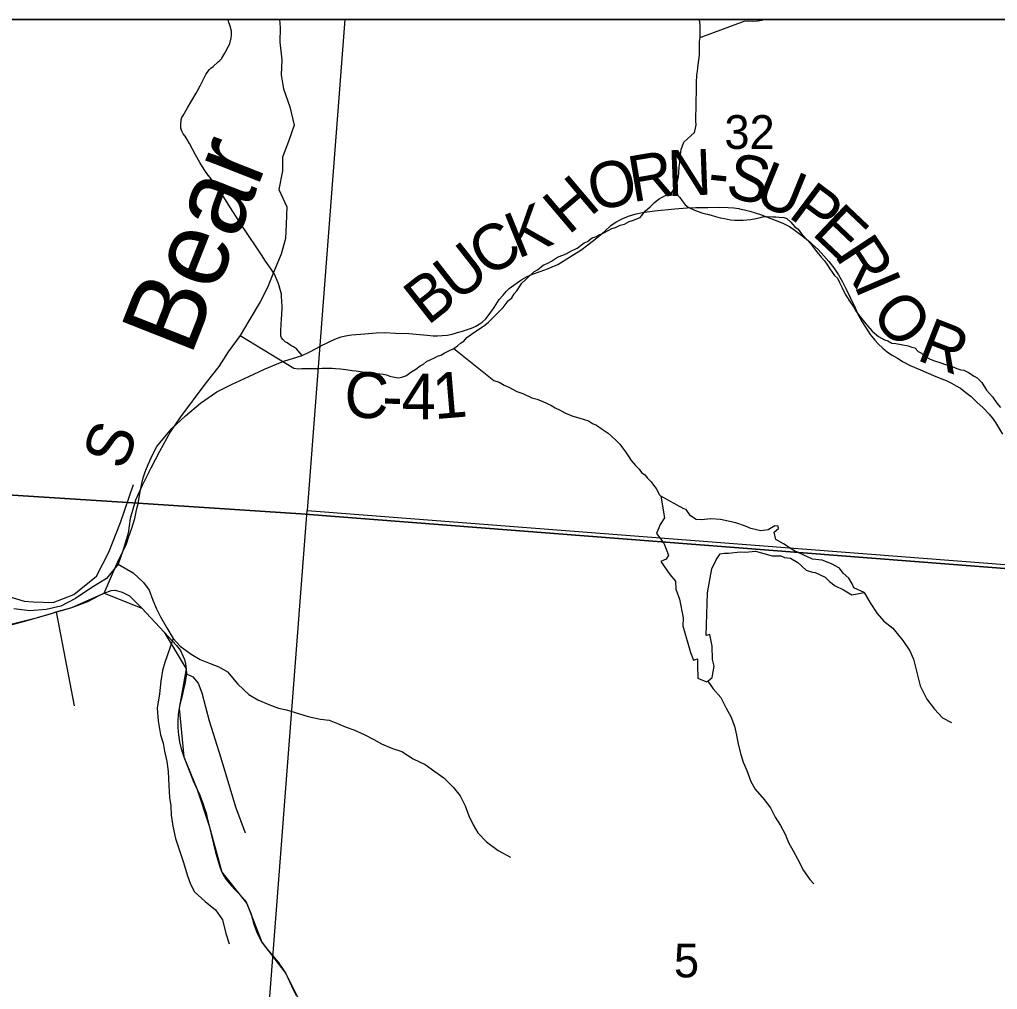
# Model space of a CAD drawing. Extents: x 0 to 82.7, y -0.2 to 22.
# Drawn here: x 6.574 to 7.785, y 19.698 to 20.9 of the extents above; entities that cross this region are included whole.
import ezdxf

# ---------------------------------------------------------------- set-up
doc = ezdxf.new("R2010")
doc.units = 0
for name, color, linetype in [('GM_X_County_Road', 7, 'Continuous'), ('GM_X_County_Road_Text', 7, 'Continuous'), ('GM_X_Minor_Lake', 7, 'Continuous'), ('GM_X_Minor_River', 7, 'Continuous'), ('GM_X_Minor_River_Text', 7, 'Continuous'), ('GM_X_Rail_Line', 7, 'Continuous'), ('GM_X_Section', 7, 'Continuous'), ('GM_X_Section_Text', 7, 'Continuous'), ('GM_X_State_Route', 7, 'Continuous'), ('GM_X_Township_Road', 7, 'Continuous'), ('GM_X_Township_Text', 7, 'Continuous'), ('SH_Cut_Line', 7, 'Continuous'), ('SH_Data', 7, 'Continuous'), ('SH_Text', 7, 'Continuous')]:
    doc.layers.add(name, color=color, linetype=linetype)

msp = doc.modelspace()

# ---------------------------------------------------------------- linework, layer by layer
at = {"layer": 'GM_X_County_Road'}
msp.add_lwpolyline([(8.0024, 20.9), (6.9771, 20.9), (6.9306, 20.2917), (7.9492, 20.2127)], close=True, dxfattribs=at)
for points in [[(6.858, 20.4576), (6.8775, 20.4666), (6.8904, 20.472), (6.9014, 20.4768), (6.9242, 20.4837), (6.9329, 20.4878), (6.9417, 20.4925), (6.9482, 20.496), (6.9553, 20.4996), (6.96, 20.5018), (6.9669, 20.5047), (6.9726, 20.5068), (6.9778, 20.5082), (6.9853, 20.5095), (7.0017, 20.5107), (7.0157, 20.5119), (7.0261, 20.5121), (7.04, 20.5115), (7.0562, 20.5111), (7.0789, 20.509), (7.0866, 20.5082), (7.0919, 20.5081), (7.0977, 20.5083), (7.1037, 20.5089), (7.1099, 20.5102), (7.1167, 20.5121), (7.1228, 20.5138), (7.1328, 20.5173), (7.136, 20.5183), (7.1395, 20.5201), (7.1434, 20.5224), (7.147, 20.5252), (7.1515, 20.5292), (7.1558, 20.5347), (7.1619, 20.5432), (7.1681, 20.5532), (7.173, 20.5586), (7.1771, 20.5634), (7.1807, 20.5667), (7.1862, 20.5709), (7.1908, 20.574), (7.1961, 20.5777), (7.203, 20.5816), (7.2093, 20.5843), (7.219, 20.5876), (7.228, 20.5911), (7.234, 20.5934), (7.2407, 20.5966), (7.2553, 20.6054), (7.2692, 20.6144), (7.2782, 20.6209), (7.2872, 20.6279), (7.2987, 20.6375), (7.3065, 20.6448), (7.3092, 20.6467), (7.3128, 20.6491), (7.3173, 20.6515), (7.3221, 20.6539), (7.3297, 20.6568), (7.3377, 20.6592), (7.3459, 20.6608), (7.3608, 20.6629), (7.3859, 20.6655), (7.401, 20.6667), (7.4117, 20.6671), (7.4265, 20.6673), (7.4394, 20.6674), (7.4519, 20.6671), (7.4587, 20.6666), (7.4649, 20.6658), (7.4659, 20.6655)], [(7.4659, 20.6655), (7.4722, 20.6643), (7.4788, 20.6625), (7.492, 20.6583), (7.5101, 20.6515), (7.5195, 20.6477), (7.523, 20.646), (7.528, 20.6434), (7.5332, 20.6398), (7.5416, 20.6337), (7.5531, 20.6246), (7.5564, 20.6214), (7.5632, 20.6149), (7.5705, 20.6074), (7.5766, 20.6001), (7.5827, 20.5922), (7.5886, 20.5835), (7.5935, 20.575), (7.5977, 20.5666), (7.6093, 20.5429), (7.613, 20.534), (7.6176, 20.5257), (7.6228, 20.5175), (7.6278, 20.5096), (7.6297, 20.5072), (7.6337, 20.5027), (7.6378, 20.4982), (7.6434, 20.4929), (7.6492, 20.4879), (7.6548, 20.4842), (7.6616, 20.4802), (7.6687, 20.476), (7.6772, 20.4714), (7.69, 20.4658), (7.7063, 20.4591), (7.7152, 20.4554), (7.7219, 20.4527), (7.7285, 20.4495), (7.7344, 20.4461), (7.7396, 20.4431), (7.7464, 20.438), (7.7529, 20.433), (7.76, 20.4258), (7.7678, 20.4188), (7.7753, 20.4112), (7.779, 20.4065), (7.7829, 20.4005), (7.7918, 20.3861)], [(6.7301, 20.3408), (6.7304, 20.3417), (6.7334, 20.3487), (6.7394, 20.3614), (6.7444, 20.3708), (6.7522, 20.3805), (6.7626, 20.3934), (6.7798, 20.4091), (6.7982, 20.4246), (6.8184, 20.4387), (6.8368, 20.4479), (6.858, 20.4576)], [(6.6791, 20.1893), (6.6935, 20.2225), (6.6984, 20.2332), (6.7063, 20.2491), (6.7097, 20.2596), (6.7133, 20.2696), (6.717, 20.2816), (6.7196, 20.2942), (6.7209, 20.3001), (6.7237, 20.3152), (6.7255, 20.325), (6.7273, 20.332), (6.7301, 20.3408)]]:
    msp.add_lwpolyline(points, dxfattribs=at)
at = {"layer": 'GM_X_Minor_Lake'}
for points in [[(7.3685, 20.3095), (7.3728, 20.2826), (7.3678, 20.2743), (7.3632, 20.263), (7.3722, 20.2512), (7.3778, 20.2363), (7.3751, 20.2314), (7.3683, 20.2284), (7.3795, 20.2124), (7.3867, 20.204), (7.387, 20.1941), (7.3914, 20.1816), (7.3962, 20.1588), (7.3958, 20.1489), (7.405, 20.1158), (7.4091, 20.1063), (7.4137, 20.1078), (7.414, 20.1002), (7.4142, 20.0839), (7.4252, 20.0793), (7.4267, 20.08), (7.4294, 20.0827), (7.4321, 20.0845), (7.4344, 20.0989), (7.4326, 20.1069), (7.4319, 20.1236), (7.429, 20.1381), (7.4245, 20.1366), (7.4263, 20.1897), (7.4295, 20.2083), (7.4315, 20.2193), (7.4368, 20.2306), (7.4418, 20.2378), (7.4471, 20.2389), (7.4524, 20.2388), (7.4665, 20.2406), (7.4733, 20.2398), (7.4858, 20.2413), (7.5062, 20.2354), (7.5172, 20.2354), (7.5217, 20.2334), (7.5289, 20.2326), (7.5383, 20.2272), (7.5485, 20.2177), (7.5564, 20.2154), (7.5598, 20.215), (7.5719, 20.2092), (7.5772, 20.2035), (7.5843, 20.1981), (7.5945, 20.1935), (7.6051, 20.1873)], [(7.6203, 20.1901), (7.6074, 20.196), (7.6055, 20.2006), (7.6011, 20.2078), (7.5943, 20.214), (7.5898, 20.2201), (7.58, 20.2254), (7.5683, 20.2301), (7.5561, 20.2313), (7.5331, 20.2421), (7.5203, 20.2505), (7.5109, 20.2555), (7.509, 20.2646), (7.514, 20.2692), (7.5136, 20.2722), (7.5095, 20.2726), (7.5015, 20.2677), (7.4924, 20.2663), (7.4799, 20.2694), (7.4735, 20.2721), (7.4614, 20.2763), (7.4425, 20.2803), (7.4304, 20.2815), (7.419, 20.2801), (7.4122, 20.2805), (7.405, 20.2851), (7.3998, 20.2927), (7.3971, 20.2939), (7.3685, 20.3095)], [(7.6051, 20.1873), (7.6203, 20.1901)]]:
    msp.add_lwpolyline(points, dxfattribs=at)
at = {"layer": 'GM_X_Minor_River'}
for points in [[(6.8961, 20.9), (6.8971, 20.8901), (6.8965, 20.8719), (6.8991, 20.8499), (6.8982, 20.8316), (6.9011, 20.8141), (6.9089, 20.7917)], [(7.3779, 20.6823), (7.3817, 20.685), (7.3848, 20.6902), (7.3879, 20.694), (7.3895, 20.7012), (7.3903, 20.705), (7.3908, 20.7103), (7.3912, 20.7175), (7.392, 20.7228), (7.3929, 20.7323), (7.3937, 20.7388), (7.3969, 20.7479), (7.4061, 20.7565), (7.4103, 20.7599), (7.4115, 20.7655), (7.4123, 20.7697), (7.412, 20.7739), (7.4117, 20.7807), (7.4122, 20.7899), (7.4123, 20.7982), (7.4128, 20.8119), (7.4125, 20.8176), (7.4125, 20.8218), (7.413, 20.8309), (7.4138, 20.8362), (7.4143, 20.84), (7.4151, 20.8472), (7.4159, 20.8525), (7.4163, 20.8563), (7.4164, 20.8658), (7.4165, 20.873), (7.417, 20.8776), (7.4171, 20.8932), (7.4165, 20.9)], [(7.417, 20.8776), (7.4718, 20.8982), (7.4771, 20.8985), (7.4821, 20.8981), (7.4881, 20.8984), (7.4939, 20.8994), (7.4949, 20.9)], [(6.9089, 20.7917), (6.9141, 20.7693), (6.9071, 20.7488), (6.8998, 20.7295), (6.8997, 20.7124), (6.8953, 20.6892), (6.9054, 20.6679), (6.9045, 20.6466), (6.9036, 20.6288), (6.8982, 20.6091), (6.8886, 20.5867), (6.8812, 20.5681), (6.872, 20.5503), (6.8582, 20.5265), (6.8475, 20.5083), (6.8325, 20.4882), (6.821, 20.4701), (6.8038, 20.4481), (6.7736, 20.4076), (6.761, 20.3895), (6.7475, 20.3649), (6.7368, 20.344), (6.726, 20.3228), (6.7179, 20.3046), (6.7113, 20.2819), (6.7086, 20.2636), (6.7027, 20.2428), (6.6962, 20.225), (6.682, 20.2072), (6.6626, 20.1955), (6.6435, 20.1827), (6.6253, 20.1729), (6.607, 20.1688), (6.5869, 20.1674), (6.5669, 20.1698)], [(6.8475, 20.5083), (6.9137, 20.4682), (6.9202, 20.4673), (6.924, 20.4677), (6.9353, 20.4675), (6.9433, 20.4678), (6.949, 20.4681), (6.9615, 20.4679), (6.9653, 20.4675), (6.9718, 20.4671), (6.9782, 20.4662), (6.9862, 20.465), (6.9911, 20.4645), (7.0009, 20.4629), (7.0066, 20.4624), (7.0104, 20.4624), (7.0165, 20.4615), (7.0244, 20.4607), (7.0286, 20.4599), (7.0327, 20.4579), (7.0365, 20.4571), (7.0437, 20.4559), (7.0475, 20.457), (7.0525, 20.4584), (7.0601, 20.4637), (7.0651, 20.4666), (7.0704, 20.4711), (7.0743, 20.473), (7.0781, 20.4763), (7.0827, 20.4782), (7.088, 20.4808), (7.0918, 20.483), (7.096, 20.4841), (7.1002, 20.4867), (7.1075, 20.4904), (7.112, 20.4923), (7.1166, 20.4956), (7.1205, 20.499), (7.1243, 20.5016), (7.1281, 20.5061), (7.1369, 20.5121), (7.1438, 20.5169), (7.1503, 20.5214), (7.1549, 20.5252), (7.1603, 20.5304), (7.1676, 20.5379), (7.1733, 20.5432), (7.1795, 20.5515), (7.1841, 20.5552), (7.1868, 20.5601), (7.1899, 20.5639), (7.1961, 20.5733), (7.2014, 20.5778), (7.211, 20.5872), (7.2156, 20.5898), (7.2225, 20.5958), (7.2286, 20.5983), (7.2332, 20.6006), (7.2404, 20.6054), (7.2511, 20.6095), (7.258, 20.6136), (7.2649, 20.6169), (7.2733, 20.6232), (7.2775, 20.6251), (7.2836, 20.6296), (7.2874, 20.6307), (7.292, 20.6333), (7.2985, 20.6362), (7.3076, 20.6411), (7.3122, 20.6425), (7.3179, 20.6451), (7.3236, 20.6466), (7.3294, 20.6499), (7.3332, 20.651), (7.3427, 20.6547), (7.3492, 20.6626), (7.3554, 20.6678), (7.3607, 20.6731), (7.3665, 20.6779), (7.3711, 20.6805), (7.3779, 20.6842), (7.3817, 20.6853), (7.3867, 20.6845), (7.3919, 20.6795), (7.3949, 20.6753)], [(7.3949, 20.6753), (7.3986, 20.6703), (7.4024, 20.6676), (7.4103, 20.6637), (7.4205, 20.6601), (7.4262, 20.6589), (7.4307, 20.6577), (7.436, 20.6558), (7.4421, 20.6542), (7.4474, 20.6533), (7.4546, 20.6517), (7.4599, 20.6513), (7.4705, 20.6515), (7.4796, 20.6522), (7.4861, 20.6536), (7.4903, 20.6543), (7.4948, 20.6554), (7.5001, 20.6561), (7.507, 20.6556), (7.5108, 20.6556), (7.5149, 20.6552), (7.5206, 20.6547), (7.5244, 20.6535), (7.5293, 20.6489), (7.5345, 20.6431), (7.5387, 20.6404), (7.5428, 20.6343), (7.5495, 20.627), (7.554, 20.6224), (7.56, 20.6143), (7.5671, 20.6055), (7.5712, 20.6012), (7.5742, 20.597), (7.5779, 20.5913), (7.5835, 20.5828), (7.5873, 20.5794), (7.5899, 20.574), (7.5932, 20.5675), (7.5969, 20.5599), (7.6025, 20.5507), (7.607, 20.5441), (7.6103, 20.5384), (7.6156, 20.5311), (7.6208, 20.525), (7.6249, 20.52), (7.6302, 20.5138), (7.638, 20.5073), (7.6456, 20.503), (7.6494, 20.5018), (7.6546, 20.4991), (7.6596, 20.4986), (7.666, 20.4974), (7.6747, 20.4958), (7.6792, 20.4942), (7.683, 20.493), (7.6872, 20.4888), (7.6913, 20.4865), (7.6954, 20.483), (7.7011, 20.4795), (7.7075, 20.4771), (7.7139, 20.4751), (7.7222, 20.472), (7.7264, 20.4712), (7.7351, 20.4677), (7.74, 20.4661), (7.7438, 20.4656), (7.7494, 20.4625), (7.7566, 20.4579), (7.7604, 20.4559), (7.766, 20.4502), (7.772, 20.4406), (7.7791, 20.4325), (7.7847, 20.4245), (7.7892, 20.4191)], [(7.112, 20.4923), (7.1617, 20.4529), (7.1681, 20.4505), (7.1745, 20.447), (7.1802, 20.4443), (7.19, 20.4392), (7.1975, 20.4368), (7.2085, 20.4314), (7.2153, 20.4294), (7.2224, 20.4266), (7.227, 20.4247), (7.2323, 20.4223), (7.2375, 20.4188), (7.2428, 20.4165), (7.2496, 20.4126), (7.2594, 20.4087), (7.267, 20.4063), (7.2734, 20.4043), (7.2787, 20.4027), (7.284, 20.3996), (7.2889, 20.3973), (7.2957, 20.3926), (7.3032, 20.3876), (7.3073, 20.3838), (7.3133, 20.3784), (7.3178, 20.3737), (7.3208, 20.3691), (7.3245, 20.3642), (7.329, 20.358), (7.3316, 20.3534), (7.3369, 20.3473), (7.3417, 20.3427), (7.3447, 20.3388), (7.3485, 20.3357), (7.3519, 20.3319), (7.3564, 20.3273), (7.3594, 20.3231), (7.3627, 20.3188), (7.3668, 20.3112), (7.3685, 20.3095)], [(6.6962, 20.225), (6.7149, 20.2143), (6.7278, 20.2025), (6.7347, 20.193), (6.7392, 20.1805), (6.7438, 20.1698), (6.7487, 20.1599), (6.7567, 20.1462), (6.7643, 20.1329), (6.773, 20.1234), (6.7867, 20.1135), (6.7977, 20.1071), (6.8102, 20.1021), (6.8209, 20.0979), (6.8319, 20.0918), (6.8444, 20.0766), (6.8581, 20.0637), (6.8695, 20.0572), (6.8828, 20.0511), (6.895, 20.0465), (6.9048, 20.0446), (6.9197, 20.0401), (6.9318, 20.0362), (6.947, 20.0332), (6.9577, 20.0317), (6.9679, 20.0278), (6.9789, 20.0233), (6.9884, 20.0198), (7.001, 20.0141), (7.0128, 20.008), (7.0223, 20.0027), (7.0359, 19.9966), (7.0477, 19.9928), (7.0618, 19.9841), (7.0766, 19.9768), (7.0884, 19.9681), (7.0998, 19.9605), (7.1112, 19.949), (7.1199, 19.938), (7.126, 19.9255), (7.1305, 19.9133), (7.1358, 19.9023), (7.1419, 19.8924), (7.1525, 19.881), (7.167, 19.8703), (7.1822, 19.8619)], [(7.6203, 20.1901), (7.6278, 20.1771), (7.6362, 20.1642), (7.6446, 20.1543), (7.6559, 20.1459), (7.6681, 20.1307), (7.6768, 20.1178), (7.6814, 20.1075), (7.6852, 20.0927), (7.6897, 20.0744), (7.6977, 20.0577), (7.7072, 20.0455), (7.7174, 20.0349), (7.7285, 20.0288)], [(6.7643, 20.1329), (6.7643, 20.1329), (6.754, 20.1033), (6.7513, 20.0934), (6.749, 20.0801), (6.7475, 20.0645), (6.7448, 20.0466), (6.7459, 20.0311), (6.7486, 20.0136), (6.752, 20.0033), (6.7535, 19.9934), (6.7566, 19.9805), (6.7584, 19.9683), (6.7592, 19.9508), (6.7599, 19.936), (6.7615, 19.9257), (6.7618, 19.9139), (6.7641, 19.9003), (6.7675, 19.885), (6.7717, 19.8717), (6.777, 19.8565), (6.7823, 19.839), (6.7857, 19.8288), (6.7907, 19.8189), (6.8039, 19.8071), (6.8169, 19.7968), (6.8256, 19.7846), (6.8298, 19.7675), (6.8336, 19.7546)], [(7.4267, 20.08), (7.4331, 20.0705), (7.4429, 20.0598), (7.4492, 20.0465), (7.4552, 20.0362), (7.4597, 20.0244), (7.4622, 20.0134), (7.4644, 20.002), (7.4674, 19.9894), (7.4703, 19.9799), (7.4748, 19.9696), (7.48, 19.9559), (7.4853, 19.9464), (7.4965, 19.9334), (7.5044, 19.9231), (7.51, 19.9117), (7.5168, 19.9014), (7.5224, 19.8904), (7.5265, 19.8801), (7.5325, 19.8698), (7.5377, 19.8599), (7.5452, 19.8455), (7.553, 19.8344), (7.5579, 19.8291)]]:
    msp.add_lwpolyline(points, dxfattribs=at)
at = {"layer": 'GM_X_Rail_Line'}
msp.add_lwpolyline([(5.9944, 20.4446), (6.0293, 20.4345), (6.1049, 20.4176), (6.1961, 20.3967), (6.2431, 20.3848), (6.2735, 20.3707), (6.3124, 20.3434), (6.437, 20.2541), (6.5007, 20.2115), (6.5467, 20.1893), (6.58, 20.1793), (6.5912, 20.1783), (6.6156, 20.1778), (6.6412, 20.1877), (6.6694, 20.2102), (6.6846, 20.24), (6.6992, 20.2769), (6.7153, 20.324)], dxfattribs=at)
at = {"layer": 'GM_X_Section'}
msp.add_lwpolyline([(6.9306, 20.2917), (7.9492, 20.2127), (7.8698, 19.2002), (6.8524, 19.275)], close=True, dxfattribs=at)
at = {"layer": 'GM_X_State_Route'}
msp.add_lwpolyline([(6.5623, 20.1494), (6.5807, 20.1547), (6.5966, 20.1592), (6.6124, 20.1636), (6.6195, 20.1661), (6.6389, 20.1715), (6.6589, 20.1788), (6.6727, 20.1861), (6.6791, 20.1893), (6.6875, 20.1924), (6.6926, 20.1929), (6.7012, 20.1906), (6.7055, 20.1885), (6.7104, 20.1857), (6.7255, 20.1707), (6.7534, 20.1407), (6.7684, 20.1245), (6.7734, 20.1183), (6.7765, 20.1117), (6.7783, 20.1071), (6.7798, 20.1015), (6.7806, 20.0954), (6.7808, 20.0892), (6.7801, 20.0838), (6.7788, 20.077), (6.7768, 20.0682), (6.7754, 20.062), (6.7729, 20.0528), (6.772, 20.0468), (6.7707, 20.0387), (6.7702, 20.0316), (6.7702, 20.022), (6.771, 20.0137), (6.7721, 20.005), (6.7744, 19.9964), (6.7778, 19.9862), (6.7821, 19.9749), (6.7894, 19.9568), (6.7941, 19.946), (6.7973, 19.9388), (6.8011, 19.9291), (6.8029, 19.9237), (6.8052, 19.917), (6.8071, 19.9089), (6.8092, 19.9007), (6.8168, 19.8683), (6.8204, 19.8555), (6.8225, 19.8487), (6.8246, 19.8436), (6.827, 19.839), (6.83, 19.8345), (6.8336, 19.8299), (6.8404, 19.8225), (6.8455, 19.8174), (6.8501, 19.8125), (6.8532, 19.8087), (6.8557, 19.8045), (6.8583, 19.7986), (6.8609, 19.7913), (6.8644, 19.7792), (6.8678, 19.77), (6.8698, 19.7652), (6.8743, 19.7569), (6.8787, 19.7505), (6.8859, 19.7421), (6.8921, 19.735), (6.8951, 19.7316), (6.8971, 19.7283), (6.9, 19.7242), (6.904, 19.7178), (6.9111, 19.7028), (6.9167, 19.6908)], dxfattribs=at)
at = {"layer": 'GM_X_Township_Road'}
msp.add_line((6.6195, 20.1661), (6.6417, 20.0497), dxfattribs=at)
for points in [[(6.9242, 20.4837), (6.9219, 20.4867), (6.9172, 20.4919), (6.9134, 20.4946), (6.9103, 20.4963), (6.9056, 20.4992), (6.9032, 20.5008), (6.9002, 20.5034), (6.8985, 20.5058), (6.8978, 20.508), (6.8978, 20.5098), (6.8979, 20.5142), (6.8983, 20.5226), (6.8986, 20.5285), (6.899, 20.5355), (6.8993, 20.5414), (6.8994, 20.5455), (6.8992, 20.5498), (6.8988, 20.5579), (6.8985, 20.5596), (6.897, 20.5655), (6.8958, 20.57), (6.8944, 20.5739), (6.892, 20.5796), (6.8898, 20.5846), (6.885, 20.592), (6.8789, 20.6004), (6.8737, 20.6083), (6.8714, 20.6122), (6.8537, 20.6384), (6.8449, 20.6519), (6.8325, 20.6712), (6.827, 20.6801), (6.8185, 20.6926), (6.8086, 20.7062), (6.8084, 20.7064), (6.8028, 20.7141), (6.7974, 20.7229), (6.7919, 20.7323), (6.7848, 20.7462), (6.7819, 20.7515), (6.7792, 20.7553), (6.7768, 20.7582), (6.7751, 20.7615), (6.7738, 20.7652), (6.7739, 20.7695), (6.7745, 20.7757), (6.7752, 20.7786), (6.7768, 20.7813), (6.7822, 20.7906), (6.7928, 20.8089), (6.798, 20.8178), (6.8047, 20.8319), (6.8056, 20.8331), (6.8076, 20.8359), (6.8095, 20.8381), (6.8111, 20.8396), (6.8138, 20.8419), (6.8202, 20.8475), (6.8224, 20.8494), (6.8236, 20.8506), (6.8242, 20.8513), (6.8249, 20.8522), (6.8286, 20.8584), (6.8326, 20.8661), (6.834, 20.869), (6.8351, 20.8721), (6.8355, 20.8738), (6.8363, 20.8774), (6.8367, 20.8805), (6.8367, 20.8829), (6.8367, 20.8857), (6.8356, 20.8902), (6.8354, 20.8908), (6.8335, 20.8962), (6.8329, 20.898), (6.8323, 20.9)], [(6.7808, 20.0892), (6.7887, 20.0854), (6.7954, 20.0777), (6.8001, 20.0656), (6.8089, 20.0311), (6.8235, 19.9853), (6.8416, 19.9246), (6.8536, 19.8923)]]:
    msp.add_lwpolyline(points, dxfattribs=at)
at = {"layer": 'GM_X_Township_Text'}
msp.add_lwpolyline([(8.9, 20.1381), (8.9, 20.9), (6.1272, 20.9), (5.9756, 20.3782), (5.9672, 20.3493), (5.9906, 20.3478), (6.0773, 20.3422), (6.1569, 20.3371), (6.2809, 20.329), (6.7144, 20.301), (6.9227, 20.2875), (7.9434, 20.2083), (8.3897, 20.1756)], close=True, dxfattribs=at)
msp.add_lwpolyline([(8.9, 14.1), (8.9, 20.1381), (8.3897, 20.1756), (7.9434, 20.2083), (6.9227, 20.2875), (6.7144, 20.301), (6.2809, 20.329), (6.1569, 20.3371), (6.0773, 20.3422), (5.9906, 20.3478), (5.9672, 20.3493), (3.6288, 20.5056)], dxfattribs=at)
at = {"layer": 'SH_Cut_Line'}
msp.add_lwpolyline([(8.9, 14.1), (8.9, 20.9), (6.1272, 20.9), (5.9756, 20.3782), (5.9672, 20.3493), (3.6288, 20.5056), (3.179, 20.5374), (2.884, 20.5583), (2.8651, 20.279), (2.8645, 20.2703), (2.8645, 20.2693), (2.8288, 19.7415), (2.7788, 19.0007), (2.7784, 18.9951), (2.7199, 18.1299), (3.0279, 17.3486), (3.0556, 17.2782), (3.2909, 16.7562), (3.4071, 16.476), (3.6125, 15.9807), (3.8036, 15.5496), (4.1209, 14.8338)], dxfattribs=at)
at = {"layer": 'SH_Data'}
msp.add_line((2.1, 20.9), (8.9, 20.9), dxfattribs=at)
at = {"layer": 'SH_Text'}
for p, q in [((6.6389, 20.1715), (6.6791, 20.1893)), ((6.6791, 20.1893), (6.7255, 20.1707)), ((6.5966, 20.1592), (6.6389, 20.1715)), ((6.7255, 20.1707), (6.7534, 20.1407)), ((6.5517, 20.1477), (6.5966, 20.1592)), ((6.7534, 20.1407), (6.7806, 20.0954)), ((6.7806, 20.0954), (6.772, 20.0468)), ((6.772, 20.0468), (6.7778, 19.9862)), ((6.7778, 19.9862), (6.7941, 19.946)), ((6.7941, 19.946), (6.8092, 19.9007)), ((6.8092, 19.9007), (6.8246, 19.8436)), ((6.8246, 19.8436), (6.8557, 19.8045)), ((6.8557, 19.8045), (6.8743, 19.7569)), ((6.8743, 19.7569), (6.904, 19.7178)), ((6.904, 19.7178), (6.9207, 19.6838))]:
    msp.add_line(p, q, dxfattribs=at)

# ---------------------------------------------------------------- texts
at = {"layer": 'GM_X_County_Road_Text'}
for s, rotation, p in [('R', 9.649, (7.3334, 20.6735)), ('N', 2.1333, (7.3775, 20.6811)), ('O', 14.387, (7.2862, 20.6613)), ('S', 347.371, (7.4468, 20.6809)), ('U', 337.8363, (7.4818, 20.6733)), ('H', 40.2209, (7.254, 20.6321)), ('-', 353.943, (7.4253, 20.6831)), ('P', 323.2717, (7.5248, 20.6563)), ('K', 22.1883, (7.1911, 20.6032)), ('E', 316.532, (7.5542, 20.6345)), ('C', 33.0985, (7.1545, 20.579)), ('R', 303.3956, (7.5828, 20.6079)), ('U', 38.0568, (7.1162, 20.549)), ('B', 38.2048, (7.0796, 20.5201)), ('I', 293.1699, (7.6073, 20.5713)), ('O', 311.0948, (7.6267, 20.5334)), ('R', 338.6875, (7.6838, 20.4787)), ('C', 357.972, (6.9757, 20.4072)), ('4', 359.4902, (7.0473, 20.4048)), ('1', 4.7978, (7.0881, 20.4047)), ('-', 358.2814, (7.0227, 20.4055)), ('S', 68.9918, (6.7036, 20.3398))]:
    msp.add_text(s, height=0.0568, rotation=rotation, dxfattribs=at).set_placement(p)
at = {"layer": 'GM_X_Minor_River_Text'}
msp.add_text('Bear', height=0.09471, rotation=68.4642, dxfattribs=at).set_placement((6.7859, 20.4812))
at = {"layer": 'GM_X_Section_Text'}
for s, height, p in [('32', 0.04186, (7.4472, 20.7397)), ('5', 0.0419, (7.3847, 19.7131))]:
    msp.add_text(s, height=height, rotation=0, dxfattribs=at).set_placement(p)

doc.saveas('drawing.dxf')
